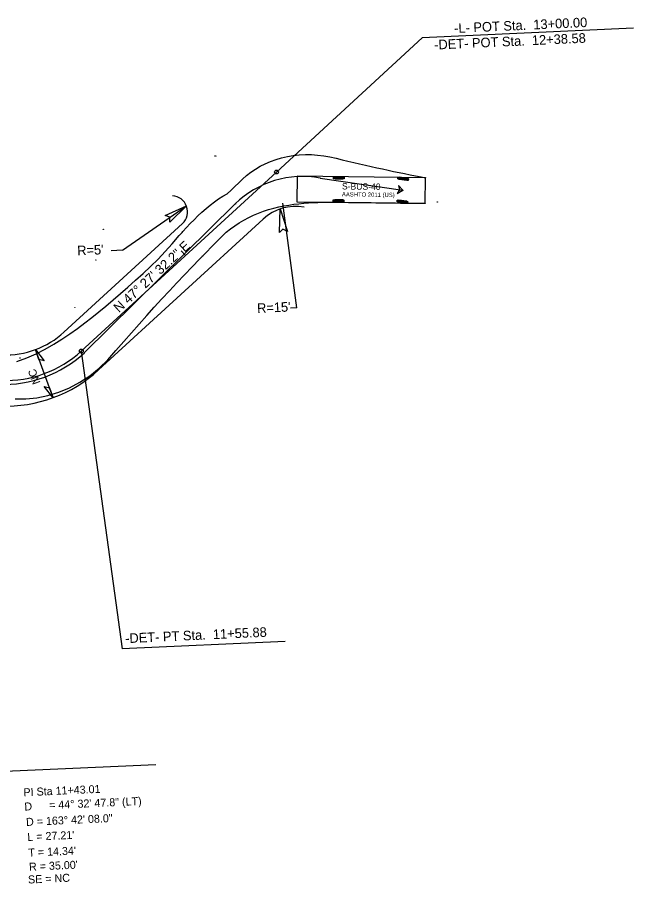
# Model space of a CAD drawing. Extents: x 1191294 to 1803985, y 659552 to 893190.
# Drawn here: x 1191501.7 to 1191694.1, y 892857 to 893127.6 of the extents above; entities that cross this region are included whole.
import ezdxf

# ---------------------------------------------------------------- set-up
doc = ezdxf.new("R2010")
doc.units = 0
for name, color, linetype in [('Prop DSN Text', 7, 'Continuous'), ('Prop EOT', 7, 'Continuous'), ('Prop Horizontal Alignment', 7, 'Continuous'), ('Prop Horizontal Alignment Curve and Spiral Data', 7, 'Continuous'), ('Prop Horizontal Alignment Direction Label', 7, 'Continuous'), ('Prop Horizontal Alignment Station Label', 7, 'Continuous'), ('Prop Horizontal Alignment Tick Small', 7, 'Continuous'), ('Prop Superelevation  Arrow CELL', 7, 'Continuous'), ('Prop Superelevation Label', 7, 'Continuous'), ('Prop Terminator CELL', 7, 'Continuous'), ('Scratch_Level_5', 7, 'Continuous'), ('Scratch_Level_9', 7, 'Continuous')]:
    doc.layers.add(name, color=color, linetype=linetype)

msp = doc.modelspace()

# ---------------------------------------------------------------- linework, layer by layer
at = {"layer": 'Prop DSN Text'}
for p, q in [((1191534.56, 893054.89), (1191554.48, 893068.78)), ((1191588.97, 893036.85), (1191584.55, 893069.56)), ((1191534.56, 893054.89), (1191530.96, 893054.72)), ((1191588.97, 893036.85), (1191586.97, 893036.76))]:
    msp.add_line(p, q, dxfattribs=at)
at = {"layer": 'Prop EOT'}
for p, q in [((1191516.27, 893029.27), (1191553.24, 893063.2)), ((1191527.09, 893017.48), (1191578.45, 893064.62))]:
    msp.add_line(p, q, dxfattribs=at)
for centre, radius, start, end in [((1191549.86, 893066.88), 5, 312.5411, 87.0448), ((1191588.59, 893053.57), 15, 79.7847, 132.5411), ((1191498.01, 893049.17), 27, 267.9944, 312.5411), ((1191498.01, 893049.17), 43, 267.9944, 312.5411)]:
    msp.add_arc(centre, radius, start, end, dxfattribs=at)
at = {"layer": 'Prop Horizontal Alignment'}
msp.add_line((1191521.68, 893023.38), (1191582.61, 893079.29), dxfattribs=at)
msp.add_arc((1191498.01, 893049.17), 35, 267.9944, 312.5411, dxfattribs=at)
at = {"layer": 'Prop Horizontal Alignment Station Label'}
for p, q in [((1191694.12, 893124.28), (1191628.14, 893121.26)), ((1191582.61, 893079.29), (1191628.14, 893121.26)), ((1191521.68, 893023.38), (1191534.43, 892930.39)), ((1191585.36, 892932.72), (1191534.43, 892930.39)), ((1191544.98, 892894.19), (1191453.47, 892890))]:
    msp.add_line(p, q, dxfattribs=at)
for centre in [(1191582.61, 893079.29), (1191521.68, 893023.38)]:
    msp.add_circle(centre, 0.6, dxfattribs=at)
at = {"layer": 'Prop Horizontal Alignment Tick Small'}
msp.add_line((1191554.18, 893053.21), (1191552.83, 893054.68), dxfattribs=at)
at = {"layer": 'Prop Superelevation  Arrow CELL'}
msp.add_line((1191512.88, 893008.82), (1191507.35, 893023.83), dxfattribs=at)
for points in [[(1191507.35, 893023.83), (1191510.12, 893020.38), (1191508.47, 893020.79)], [(1191512.88, 893008.82), (1191510.12, 893012.28), (1191511.76, 893011.86)]]:
    msp.add_lwpolyline(points, close=True, dxfattribs=at)
at = {"layer": 'Prop Terminator CELL'}
for points in [[(1191547.87, 893065.68), (1191554.48, 893068.78), (1191549.28, 893063.59), (1191549.3, 893065.17)], [(1191583.51, 893060.46), (1191583.74, 893067.76), (1191586.01, 893060.77), (1191584.62, 893061.5)]]:
    msp.add_lwpolyline(points, close=True, dxfattribs=at)
at = {"layer": 'Scratch_Level_5'}
for centre in [(1191563.38, 893084.28), (1191563.38, 893084.28), (1191632.8, 893069.93), (1191526.26, 893051.86), (1191526.26, 893051.86), (1191502.56, 893021.22), (1191502.56, 893021.22)]:
    msp.add_circle(centre, 0.0417, dxfattribs=at)
at = {"layer": 'Scratch_Level_9'}
for p, q in [((1191589.11, 893078.04), (1191589, 893070.04)), ((1191629.1, 893077.52), (1191589.11, 893078.04)), ((1191596.26, 893077.42), (1191622.05, 893073.61)), ((1191603.77, 893077.64), (1191600.43, 893077.69)), ((1191603.77, 893077.43), (1191600.43, 893077.48)), ((1191603.76, 893077.23), (1191600.43, 893077.27)), ((1191623.77, 893076.75), (1191620.47, 893077.22)), ((1191623.8, 893076.95), (1191620.5, 893077.43)), ((1191623.83, 893077.16), (1191620.53, 893077.64)), ((1191629, 893069.52), (1191629.1, 893077.52)), ((1191629.1, 893077.52), (1191629.1, 893077.52)), ((1191522.62, 893022.82), (1191569.74, 893069.34)), ((1191589, 893070.04), (1191629, 893069.52)), ((1191603.67, 893070.48), (1191600.34, 893070.52)), ((1191603.67, 893070.27), (1191600.34, 893070.31)), ((1191603.67, 893070.06), (1191600.34, 893070.1)), ((1191623.56, 893069.58), (1191620.27, 893070.08)), ((1191623.59, 893069.79), (1191620.3, 893070.28)), ((1191623.63, 893069.99), (1191620.33, 893070.49))]:
    msp.add_line(p, q, dxfattribs=at)
for points in [[(1191553.17, 893060.43), (1191553.4, 893060.68), (1191554.54, 893061.93), (1191555.7, 893063.17), (1191556.89, 893064.39), (1191558.1, 893065.59), (1191559.34, 893066.76), (1191560.61, 893067.89), (1191561.9, 893068.99), (1191563.23, 893069.94), (1191564.55, 893070.92), (1191565.87, 893071.8), (1191567.21, 893072.52), (1191568.43, 893073.62), (1191569.63, 893074.77), (1191570.84, 893075.92), (1191572.04, 893077.07), (1191573.28, 893078.2), (1191574.62, 893079.25), (1191576.04, 893080.22), (1191577.55, 893081.11), (1191579.12, 893081.9), (1191580.77, 893082.6), (1191582.47, 893083.21), (1191584.22, 893083.72), (1191586.02, 893084.13), (1191587.86, 893084.43), (1191589.73, 893084.63), (1191591.62, 893084.73), (1191593.53, 893084.72), (1191595.45, 893084.6), (1191597.37, 893084.37), (1191599.29, 893084.03), (1191601.2, 893083.59), (1191603.08, 893083.13), (1191604.93, 893082.69), (1191606.76, 893082.26), (1191608.58, 893081.84), (1191610.38, 893081.43), (1191612.16, 893081.03), (1191613.93, 893080.63), (1191615.69, 893080.25), (1191617.43, 893079.87), (1191619.17, 893079.5), (1191620.9, 893079.14), (1191622.62, 893078.79), (1191624.33, 893078.45), (1191626.04, 893078.11), (1191627.74, 893077.78), (1191629.1, 893077.52)], [(1191559.56, 893053.07), (1191559.79, 893053.31), (1191560.98, 893054.52), (1191562.16, 893055.73), (1191563.34, 893056.94), (1191564.52, 893058.14), (1191565.71, 893059.35), (1191566.89, 893060.55), (1191568.23, 893061.55), (1191569.61, 893062.52), (1191571.01, 893063.44), (1191572.46, 893064.3), (1191573.93, 893065.1), (1191575.44, 893065.84), (1191576.98, 893066.5), (1191578.55, 893067.09), (1191580.14, 893067.6), (1191581.75, 893068.04), (1191583.36, 893068.41), (1191584.95, 893068.72), (1191586.52, 893068.99), (1191588.08, 893069.21), (1191589.62, 893069.39), (1191591.13, 893069.53), (1191592.63, 893069.65), (1191594.1, 893069.74), (1191595.54, 893069.81), (1191596.97, 893069.85), (1191598.38, 893069.88), (1191599.76, 893069.89), (1191601.12, 893069.88), (1191602.47, 893069.87), (1191603.8, 893069.85), (1191605.11, 893069.83), (1191606.45, 893069.82), (1191607.83, 893069.8), (1191609.24, 893069.78), (1191610.68, 893069.76), (1191612.15, 893069.74), (1191613.64, 893069.72), (1191615.15, 893069.7), (1191616.68, 893069.68), (1191618.22, 893069.66), (1191619.78, 893069.64), (1191621.34, 893069.62), (1191622.92, 893069.6), (1191624.51, 893069.58), (1191626.11, 893069.56), (1191627.71, 893069.54), (1191629, 893069.52)], [(1191501.52, 893020.14), (1191504.63, 893021.24), (1191507.59, 893022.54), (1191510.4, 893023.98), (1191513.08, 893025.52), (1191515.65, 893027.12), (1191518.1, 893028.78), (1191520.47, 893030.46), (1191522.75, 893032.16), (1191524.97, 893033.87), (1191527.12, 893035.6), (1191529.34, 893037.42), (1191531.61, 893039.34), (1191533.91, 893041.33), (1191536.24, 893043.38), (1191538.59, 893045.48), (1191540.95, 893047.63), (1191543.32, 893049.8), (1191545.67, 893052.04), (1191547.87, 893054.46), (1191550.08, 893056.91), (1191552.28, 893059.43), (1191553.17, 893060.43)], [(1191500.99, 893008.49), (1191504.37, 893008.46), (1191507.8, 893008.78), (1191511.23, 893009.46), (1191514.64, 893010.51), (1191517.99, 893011.9), (1191521.23, 893013.62), (1191524.33, 893015.67), (1191527.27, 893018.01), (1191530, 893020.63), (1191532.5, 893023.51), (1191534.94, 893026.35), (1191537.34, 893029.12), (1191539.73, 893031.82), (1191542.1, 893034.48), (1191544.46, 893037.09), (1191546.82, 893039.66), (1191549.18, 893042.19), (1191551.53, 893044.7), (1191553.89, 893047.18), (1191556.25, 893049.65), (1191558.61, 893052.09), (1191559.56, 893053.07)]]:
    msp.add_lwpolyline(points, dxfattribs=at)
for points in [[(1191603.77, 893077.69), (1191603.76, 893077.18), (1191603.29, 893077.02), (1191600.89, 893077.06), (1191600.43, 893077.22), (1191600.44, 893077.74), (1191600.9, 893077.89), (1191603.3, 893077.86)], [(1191623.84, 893077.21), (1191623.76, 893076.69), (1191623.28, 893076.61), (1191620.9, 893076.95), (1191620.46, 893077.17), (1191620.54, 893077.69), (1191621.02, 893077.78), (1191623.4, 893077.43)], [(1191622.05, 893073.61), (1191620.66, 893075.05), (1191621.06, 893073.76), (1191620.3, 893072.64)], [(1191603.67, 893070.53), (1191603.67, 893070.01), (1191603.2, 893069.86), (1191600.8, 893069.89), (1191600.34, 893070.05), (1191600.34, 893070.57), (1191600.81, 893070.72), (1191603.21, 893070.69)], [(1191623.63, 893070.04), (1191623.56, 893069.53), (1191623.07, 893069.44), (1191620.7, 893069.8), (1191620.26, 893070.03), (1191620.34, 893070.54), (1191620.82, 893070.63), (1191623.2, 893070.27)]]:
    msp.add_lwpolyline(points, close=True, dxfattribs=at)
for centre in [(1191563.7, 893084.26), (1191563.7, 893084.26), (1191596.26, 893077.42), (1191596.26, 893077.42), (1191629.1, 893077.52), (1191622.05, 893073.61), (1191569.74, 893069.34), (1191569.74, 893069.34), (1191629, 893069.52), (1191632.8, 893069.93), (1191528.58, 893061.37), (1191528.58, 893061.37), (1191553.17, 893060.43), (1191553.17, 893060.43), (1191559.56, 893053.07), (1191559.56, 893053.07), (1191519.66, 893037.02), (1191519.66, 893037.02), (1191522.62, 893022.82), (1191522.62, 893022.82)]:
    msp.add_circle(centre, 0.0417, dxfattribs=at)
for centre, radius, start, end in [((1191590.81, 893047.75), 30.17, 79.5963, 134.3037), ((1191497.32, 893050.39), 37.43, 267.9944, 312.5411)]:
    msp.add_arc(centre, radius, start, end, dxfattribs=at)

# ---------------------------------------------------------------- texts
at = {"layer": 'Prop DSN Text'}
for s, p in [("R=5'", (1191520.47, 893053.25)), ("R=15'", (1191576.62, 893035.27))]:
    msp.add_text(s, height=3, rotation=2.6195, dxfattribs=at).set_placement(p)
at = {"layer": 'Prop Horizontal Alignment Curve and Spiral Data'}
for s, p in [('PI Sta 11+43.01', (1191503.68, 892884.31)), ('= 44%%d 32\' 47.8" (LT)', (1191511.69, 892880.31)), ('D', (1191503.96, 892879.85)), ('D = 163%%d 42\' 08.0"', (1191504.48, 892875.06)), ("L = 27.21'", (1191504.89, 892870.36)), ("T = 14.34'", (1191505.21, 892865.47)), ("R = 35.00'", (1191505.41, 892861.05)), ('SE = NC', (1191505.1, 892857.06))]:
    msp.add_text(s, height=2.5, rotation=2.6195, dxfattribs=at).set_placement(p)
at = {"layer": 'Prop Horizontal Alignment Direction Label'}
msp.add_text('N 47%%d 27\' 32.2" E', height=3, rotation=42.5411, dxfattribs=at).set_placement((1191533.42, 893035.23))
at = {"layer": 'Prop Horizontal Alignment Station Label'}
for s, p in [('-L- POT Sta.  13+00.00', (1191638.14, 893122.7)), ('-DET- POT Sta.  12+38.58', (1191631.91, 893117.54)), ('-DET- PT Sta.  11+55.88', (1191535.43, 892932.14))]:
    msp.add_text(s, height=3, rotation=2.6195, dxfattribs=at).set_placement(p)
at = {"layer": 'Prop Superelevation Label'}
msp.add_text('NC', height=2.5, rotation=110.2342, dxfattribs=at).set_placement((1191508.97, 893013.53))
at = {"layer": 'Scratch_Level_9'}
for s, height, p in [('S-BUS-40', 2, (1191603.05, 893073.86)), ('AASHTO 2011 (US)', 1.3333, (1191603.04, 893071.69))]:
    msp.add_text(s, height=height, rotation=359.2518, dxfattribs=at).set_placement(p)

doc.saveas('drawing.dxf')
